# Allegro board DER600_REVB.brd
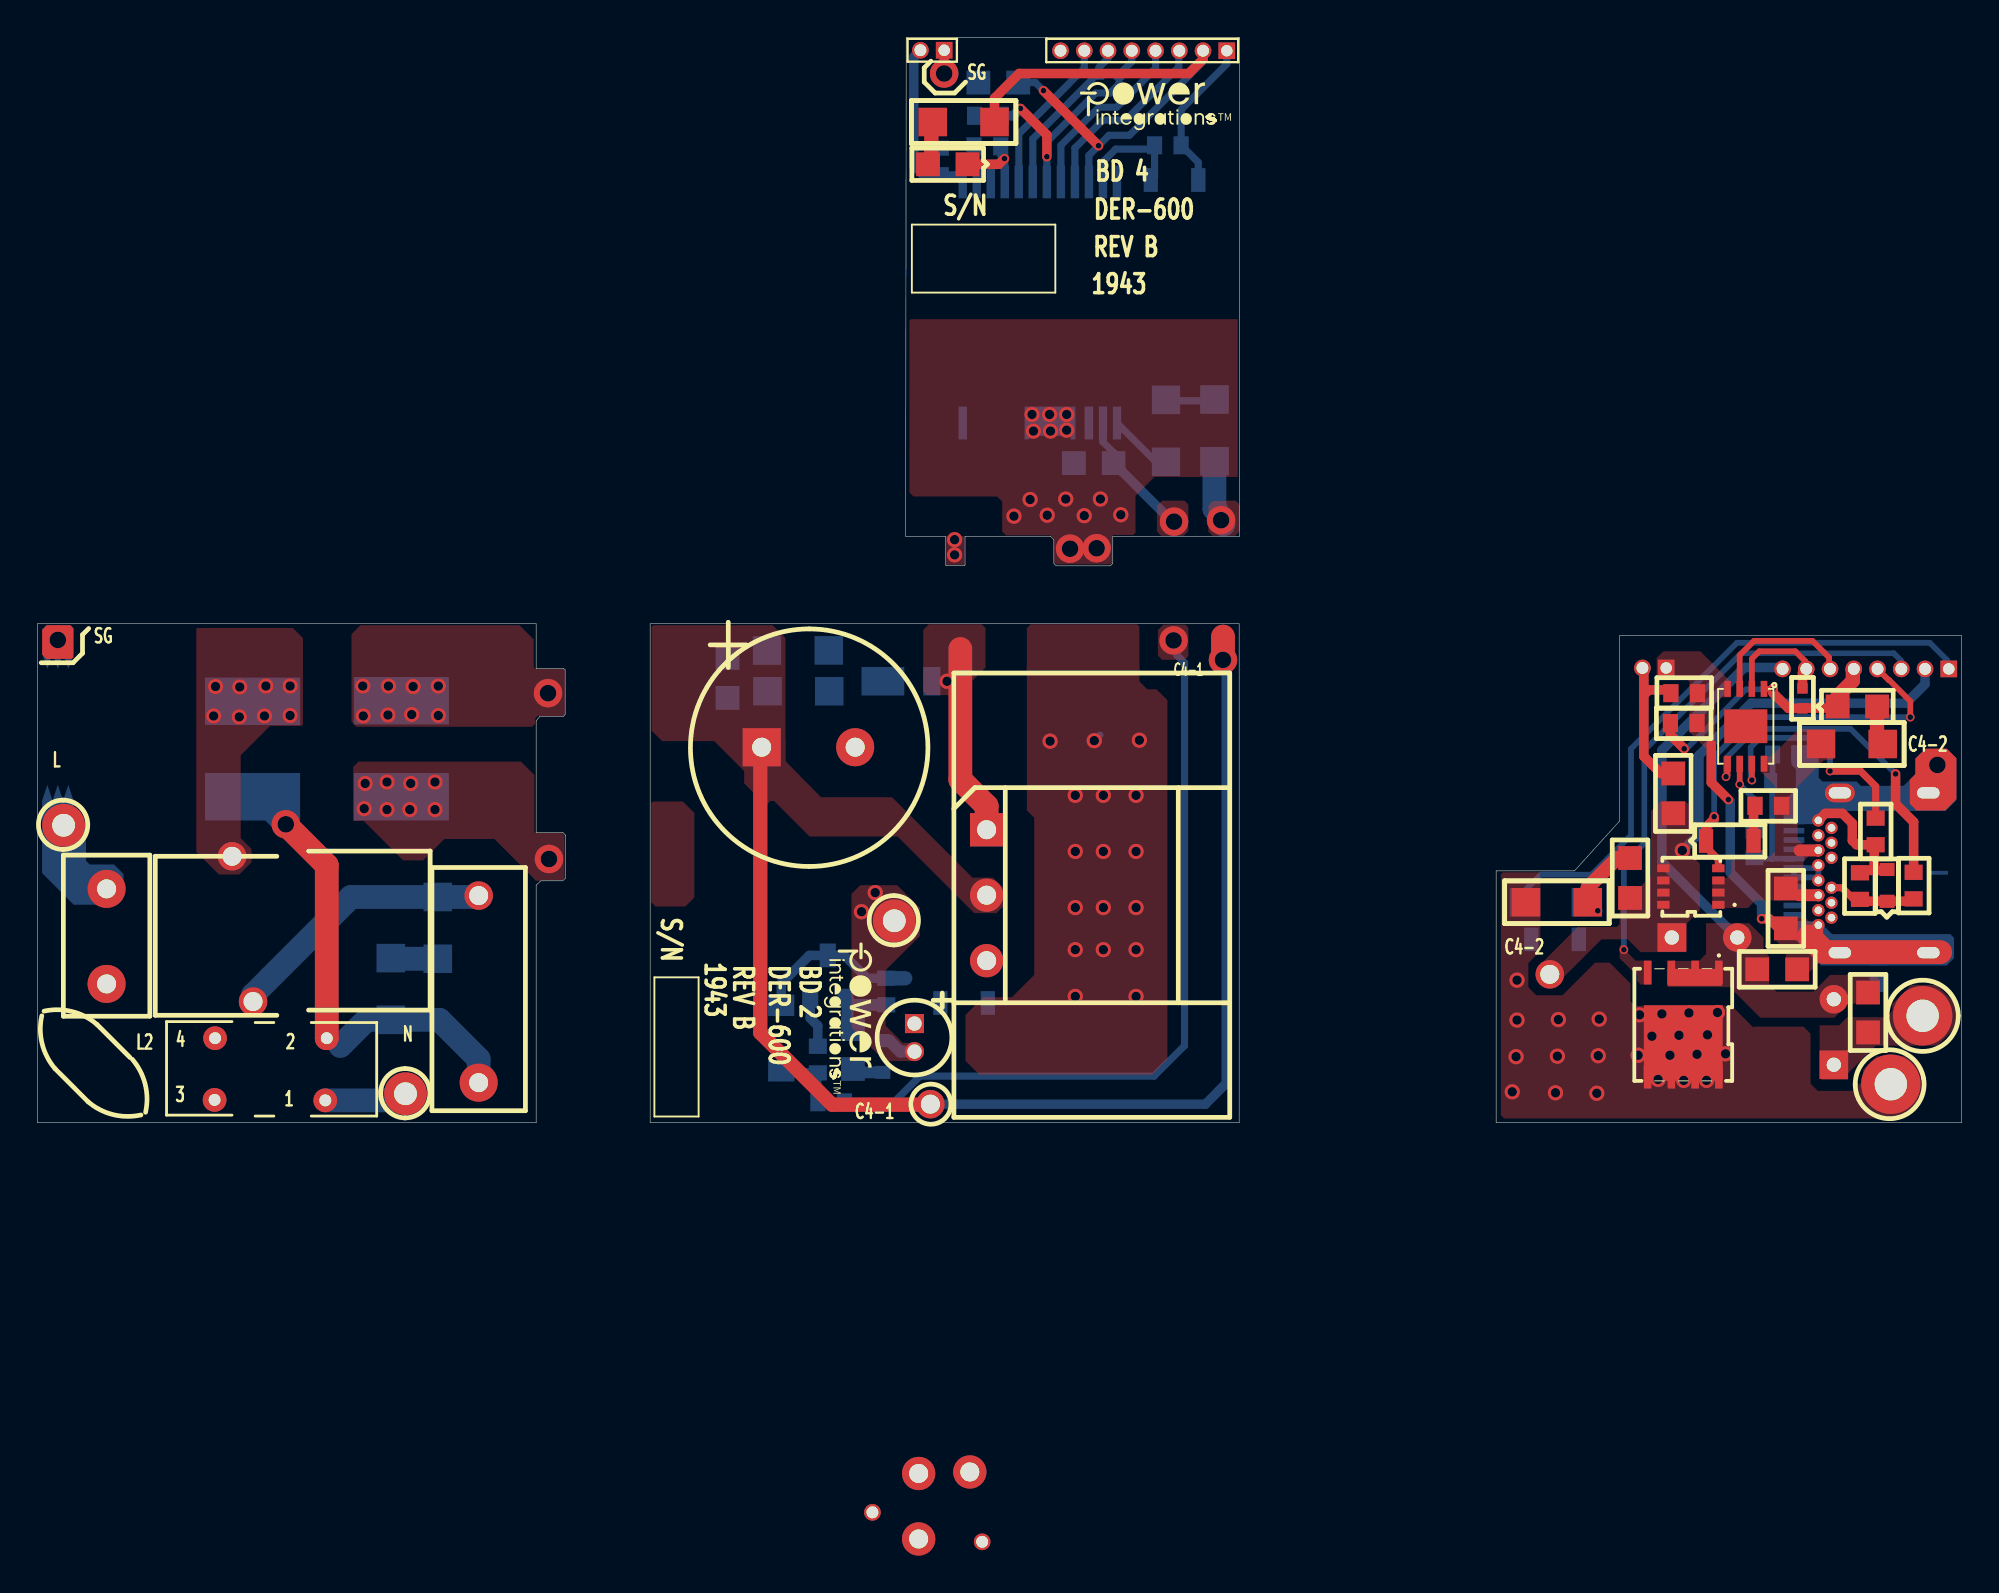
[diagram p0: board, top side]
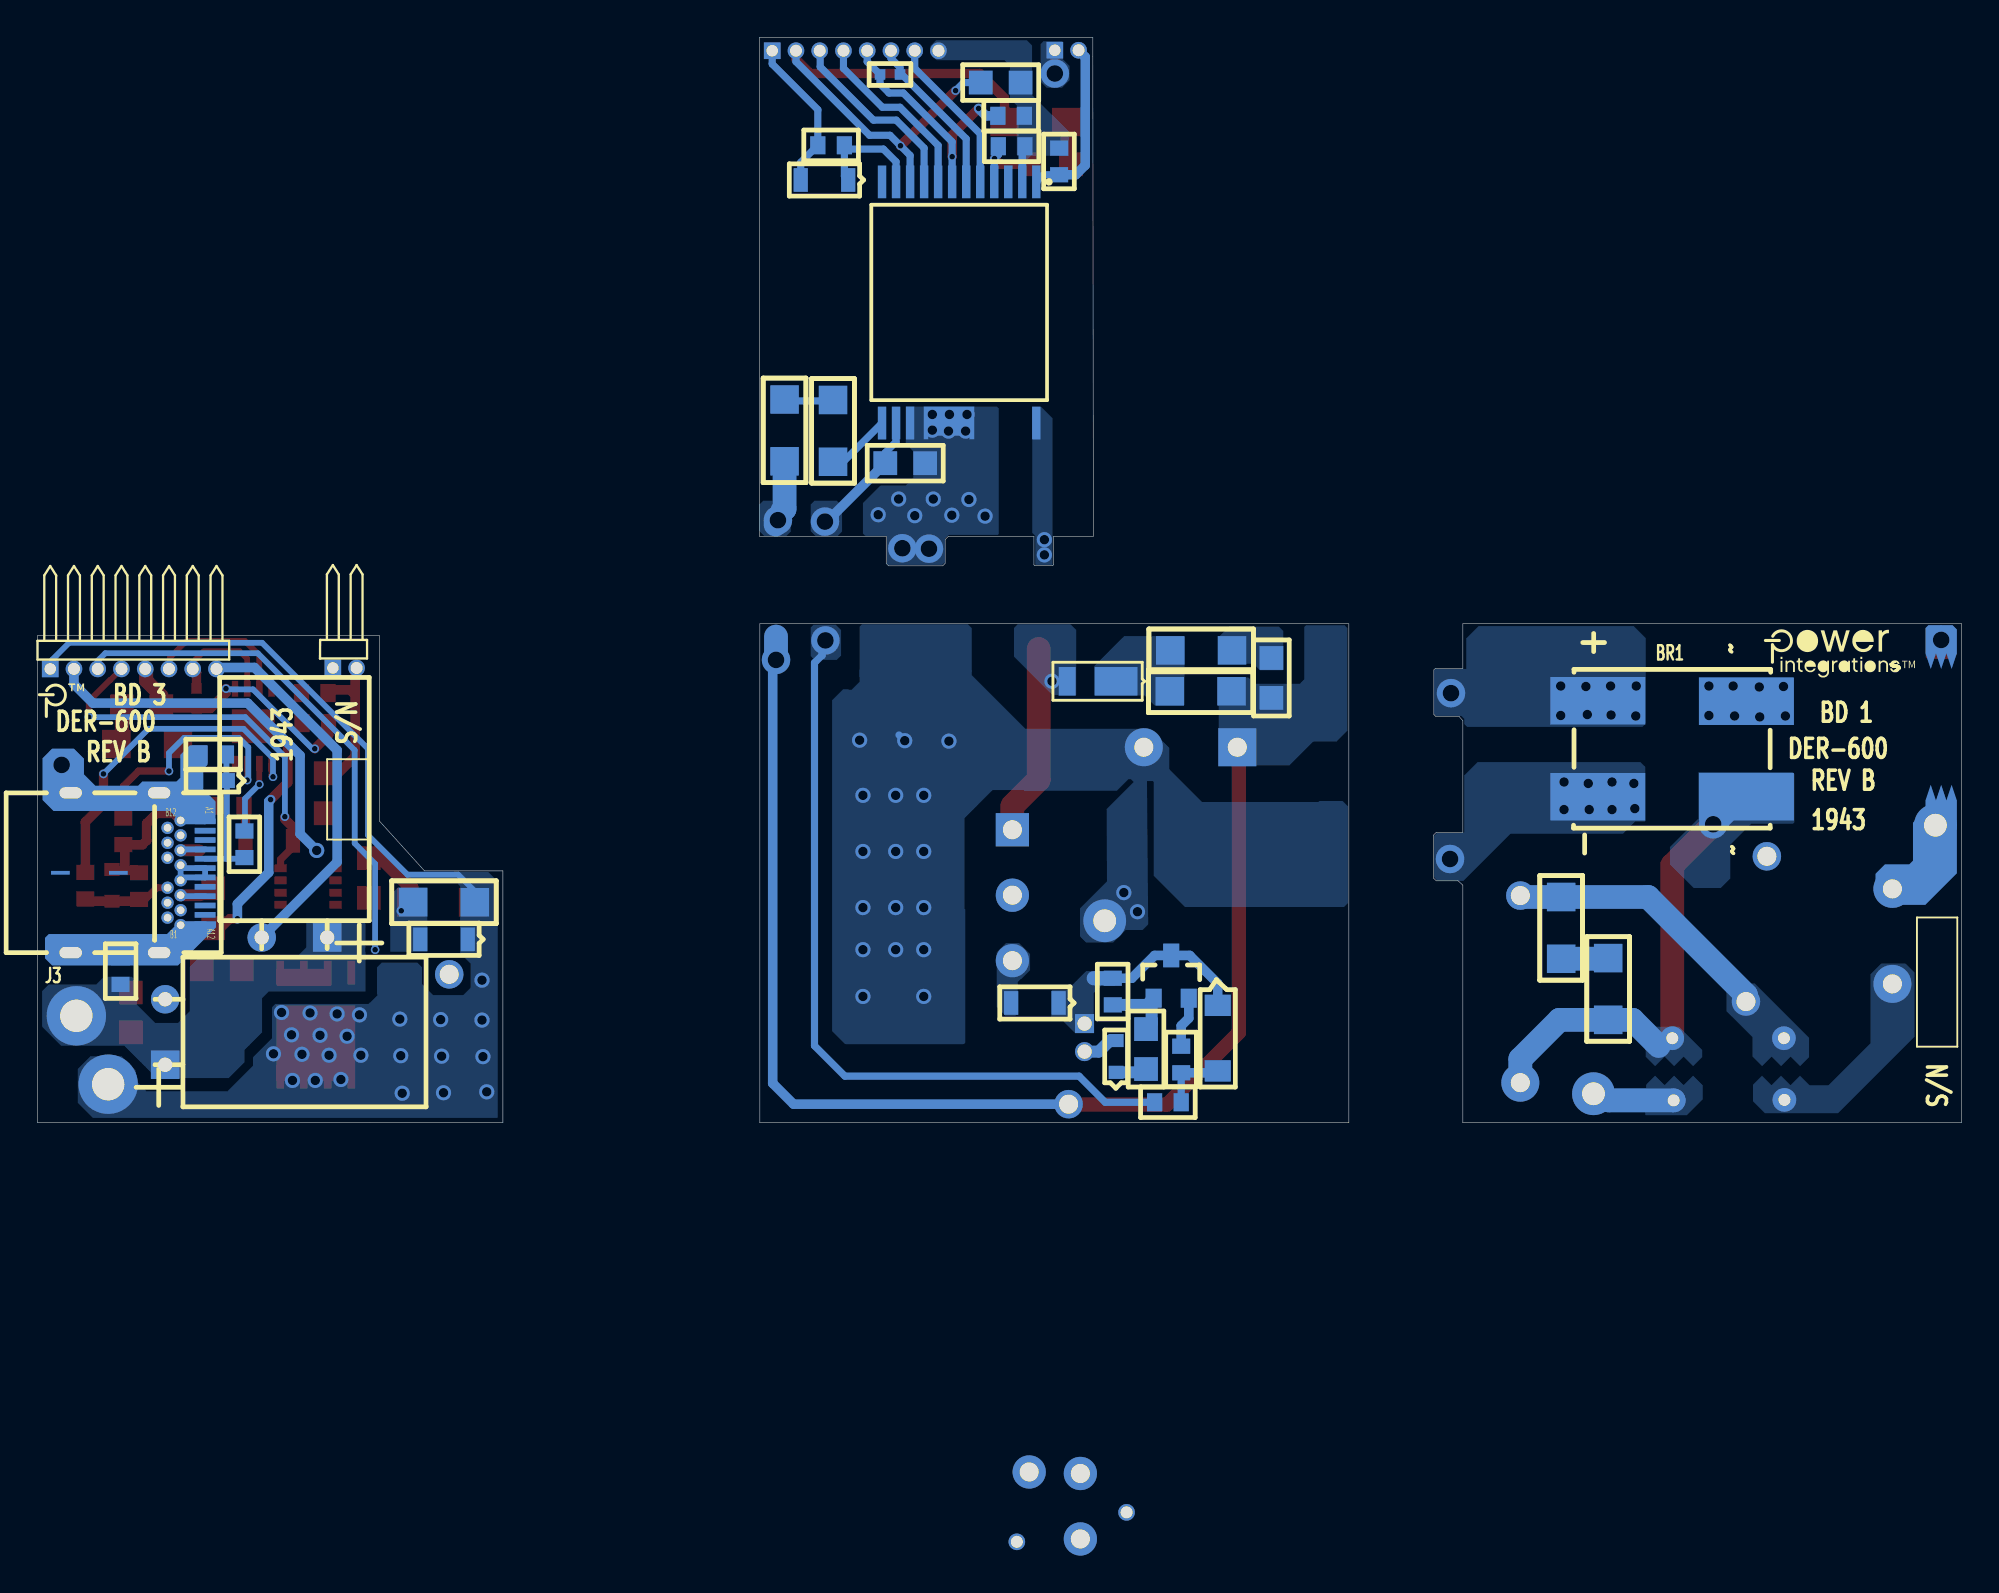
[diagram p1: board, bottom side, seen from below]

Outline 102.9 x 58.01 mm; copper layers: TOP, BOTTOM. Coordinates in mm from the lower left corner of the outline.
Outline path: 0,26.67 26.67,26.67 26.67,24.28 28.14,24.28 28.22,24.21 28.22,21.82 28.12,21.72 26.87,21.72 26.67,21.49 26.67,15.52 28.09,15.52 28.24,15.37 28.24,13.08 28.09,12.93 26.92,12.93 26.67,12.7 26.67,0 0,0 0,26.67 ; 32.77,26.67 64.26,26.67 64.26,0 32.77,0 32.77,26.67 ; 46.43,31.34 46.46,56.97 46.46,58.01 64.29,58.01 64.29,31.34 57.51,31.34 57.51,29.9 57.38,29.77 54.48,29.77 54.36,29.9 54.36,31.17 54.18,31.34 49.61,31.34 49.61,29.82 49.58,29.79 48.59,29.79 48.56,29.82 48.56,31.34 46.43,31.34 ; 78,13.46 82.19,13.46 84.61,16.13 84.61,26.04 102.9,26.04 102.9,0 78,0 78,13.46

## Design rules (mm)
constraint set DEFAULT: min track width 0.508

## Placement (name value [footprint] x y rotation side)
BR1  Z4DGP408L-HF  [PI_SM_D_Z4D]  19.51 22.53 90 bottom
C1  0.1 uF  [PINPXCAPRAD5X13X11P1MM040]  23.6 12.14 270 top
C2  56 uF  [PIPOLCAPCLYD500LS200040]  38.73 20.07 0 top
C3  2.2 nF  [PISMC0805]  36.91 22.71 90 bottom
C4  470 pF  [PINPCAPRAD7P5X11P5LS7P5MM030]  80.87 0.43 90 top
C5  6.8 uF  [PIPOLCAP4P0X11P0XLS1P5D030]  46.9 5.3 270 top
C6  4.7 uF  [PISMC0805]  57.56 35.26 180 bottom
C7  2.2 uF  [PISMC0603]  51.51 52.2 180 bottom
C8  4.7uF  [PISMC0603]  48.26 52.1 270 bottom
C9  3.3 uF-DNP  [PISMC0805]  50.32 55.6 0 bottom
C10  2.2 uF  [PISMC0603]  50.11 53.82 0 bottom
C11  1 nF  [PISMC0805]  85.17 14.15 270 top
C12  330 uF  [PIPOLCAPCYLD315LS138D030#2]  97.61 3.1 90 top
C14  2.2 uF  [PISMC0603]  87.33 21.36 0 top
C15  10 uF  [PISMC0805]  93.5 12.52 270 top
C16  560 pF  [PISMC0603]  94.21 19.68 180 bottom
C17  560 pF  [PISMC0603]  97.46 13.36 270 top
C19  2.2 uF  [PISMC0805]  97.89 6.96 270 top
C20  330 uF  [PIPOLCAPCYLD315LS138D030]  87.4 8.3 0 top
C21  1 uF  [PISMC0603]  98.45 7.39 90 bottom
D1  DFLF1800-7  [PISMDDFLR120012]  45.19 23.6 180 bottom
D2  BAV3004WS-7  [PISMSOD323]  48.29 6.4 0 bottom
D3  BAV19WS  [PISMSOD323]  79.88 9.8 0 bottom
D4  BAV21WS-7-F  [PISMSOD323]  89.23 15.06 0 top
D5  DZ2J240M0L  [PI_SM_D_SSMINI2P]  98.91 11.84 90 top
D6  DZ2J240M0L  [PI_SM_D_SSMINI2P]  92.68 18.29 0 bottom
D7  BAS416,115  [PISMDSOD323]  96.27 22.25 0 top
D8  BAS416,115-DNP  [PISMDSOD323]  49.73 51.23 180 top
D9  BAV19WS  [PISMSOD323]  59.54 50.39 0 bottom
F1  3.15 A  [PI_RST_MICROFUSE]  3.7 12.5 270 top
FL1  Hole_70mils  [PI_HOLE_70MIL]  100.84 5.71 90 top
FL2  Hole_70mils  [PI_HOLE_70MIL]  99.14 2.06 90 top
FL3  Hole_50mils  [PI_HOLE_50MIL]  45.82 10.79 0 top
J1  PCB Terminal 22 AWG  [PI_HOLE_22AWG]  1.4 15.9 0 top
J2  PCB Terminal 22 AWG  [PI_HOLE_22AWG]  19.68 1.55 0 top
J3  CON24_USB_C  [PI_CONN_USBC_WURTH]  95.94 13.36 270 bottom
J4  CON8  [PI_HDR_1P27MM_8RA]  63.6 57.3 180 top
J5  CON8  [PI_HDR_1P27MM_8RA]  102.21 24.26 180 bottom
J6  CON3  [PI_HDR_1P27MM_3RA]  48.49 57.33 180 top
J7  CON3  [PI_HDR_1P27MM_3RA#2]  87.1 24.31 180 bottom
L1  150 uH  [PI2P16P5X8P5X8P5LSD60]  12.75 6.02 90 top
L2  250 uH  [PI_TOROID_CMC4P_V_275UH]  13.64 0.36 180 top
NOREF  -  []  78 0 0 top
NOREF#2  -  []  64.29 31.34 90 top
NOREF#3  -  []  32.77 0 0 top
NOREF#4  -  []  102.9 0 90 top
NOREF#5  -  []  0 0 90 top
NOREF#6  -  []  -223.24 -184.18 0 top
NOREF#7  -  []  55.19 55.52 0 top
NOREF#8  -  []  44.53 10.19 270 top
NOREF#9  -  []  46.46 56.97 0 top
NOREF#10  -  []  0 26.67 0 top
NOREF#11  -  []  -154.42 52.58 0 top
NOREF#12  -  []  11.13 26.26 180 bottom
NOREF#13  -  []  102.77 23.7 180 bottom
Q1  MMBTA06LT1G  [PISMSOT23123_1]  41.33 6.65 180 bottom
Q2  AON6220  [PISMPQFN5X6B]  89.92 8.03 180 top
Q3  AON7520  [PISM8DFN_EP3P3X3P3A]  88.42 12.62 90 top
R1  1 M  [PISMR1206]  21.41 12.06 270 bottom
R2  1 M  [PISMR1206]  18.9 8.8 270 bottom
R4  2.00 M  [PISMR1206]  62.94 38.66 270 bottom
R5  1.80 M  [PISMR1206]  60.35 35.33 90 bottom
R6  20  [PISMR1206]  42.32 25.25 180 bottom
R7  680 k  [PISMR1206]  39.04 23.06 0 bottom
R8  100 k  [PISMR0603]  45.39 7.72 270 bottom
R9  5.1 k  [PISMR0805]  43.61 5 270 bottom
R10  3 k  [PISMR0603]  41.73 4.09 270 bottom
R11  47  [PISMR0603]  41.73 1.09 0 bottom
R12  20  [PISMR1206]  82.91 11.79 180 top
R13  20  [PISMR1206]  82.8 11.79 180 bottom
R14  47  [PISMR0603]  61.16 52.25 180 bottom
R15  0.009  [PISMR0805]  94.1 8.2 180 top
R16  324 k  [PISMR0805]  87.48 16.54 90 top
R17  10  [PISMR0603]  88.77 22.96 180 top
R18  4.70 k -DNP  [PISMR0402]  57.84 56.03 180 bottom
R19  4.70 k-DNP  [PISMR0402]  94.39 22.15 90 top
R20  1.5 k  [PISMR1206]  95.38 20.24 0 top
R21  1.5 k-DNP  [PISMR1206]  51.18 53.49 180 top
R22  100  [PISMR0603]  91.85 16.94 0 top
R23  22  [PISMR0603]  91.82 15.6 270 bottom
R24  22  [PISMR0603]  100.33 11.96 90 top
RT1  100 k  [PISMR0603]  98.3 14.86 90 top
T1  ATQ23.7/14  [PI_BOBBIN_ATQ23_7_H_6P]  56.38 12.16 0 top
U1  INN3368C-H301-TL  [PI_IC_INSOP_24D]  49.48 50.29 270 bottom
U2  VP302  [PI_SM_DFN-8]  92.33 23.19 180 top
VR1  MMSZ5261BT1G  [PI_SM_SOD-123_12]  39.78 6.27 270 bottom
VR2  DZ2S100M0L  [PI_SM_D_SSMINI2P]  45.21 2.69 90 bottom

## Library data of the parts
BR1 = DISCRETE BRIDGE_+~~-
C1 = CAP NP: alternate symbols: (pinpxcaprad5x13x11p1mm040h)
C2 = CAP POL: alternate symbols: (pipolcapclyd500ls2000401000lh)
C3 C4 C6 C8 C9 C19 = CAP NP
C5 = CAP POL: alternate symbols: (pipolcap4p0x11p0xls1p5d030h)
C7 C10 C14 C21 = CAP NP: alternate symbols: (pismc0603_1)
C11 = CAP NP: alternate symbols: (pismc0805_1)
C12 C20 = CAP POL: alternate symbols: (pipolcapcyld315ls138d030h)
C15 = CAP NP: alternate symbols: (pismc0805_1); room: 3
C16 C17 = CAP NP: room: 3
D1 = DIODE: alternate symbols: (pismddflr120012_1)
D2-D4 D7-D9 = DIODE
D5 D6 = DIODE_ZENER: room: 3
F1 = FUSE: alternate symbols: (pirstmicrofusehoz)
FL1-FL3 = FlyingLead
J1 J2 = TERM_1Pin
J3 = CON24_USB: room: 3
J4 J5 = CON8
J6 J7 = CON3
L1 = INDUCTOR
L2 = TORRID 4P_12_34: alternate symbols: (pi_toroid_CMC4p_V,pi_toroid_CMC4p_V_275uH)
Q1 = NPN_BEC
Q2 Q3 = FET_N_SGD_123_4_5678
R1 R2 R4-R22 = R
R23 R24 = R: room: 3
RT1 = THERMISTOR: room: 3
T1 = BATQ23_7_6P/GENERIC
U1 = InnoPro_p15
U2 = VP302: room: 3
VR1 VR2 = DIODE_ZENER

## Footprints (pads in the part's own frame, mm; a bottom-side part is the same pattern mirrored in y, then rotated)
PI2P16P5X8P5X8P5LSD60
  round 1.524 hole 1.016: 1(0.457,1.219) 2(8.221,2.337)
PI_BOBBIN_ATQ23_7_H_6P
  rect 1.778x1.778 hole 1.016: 1(-5.625,3.5)
  round 1.778 hole 1.016: 2(-5.625,0) 3(-5.625,-3.5) 4(-9.259,-34.412) 5(-9.259,-30.912) 6(-6.523,-30.831)
PI_CONN_USBC_WURTH
  oval 1.001x1.6 hole 0.599x1.199: (-4.27,-5.18) (-4.27,-0.45) (4.27,-5.18) (4.27,-0.45)
  round 0.66 hole 0.406: (-2,0.7) (2,0.7) B1(2.8,0.7) B2(2.4,0) B3(1.6,0) B4(1.2,0.7) B5(0.8,0) B6(0.4,0.7) B7(-0.4,0.7) B8(-0.8,0) B9(-1.2,0.7) B10(-1.6,0) B11(-2.4,0) B12(-2.8,0.7)
  rect 0.305x1.118 smd: A1(-2.75,2.01) A2(-2.25,2.01) A3(-1.75,2.01) A4(-1.25,2.01) A5(-0.75,2.01) A6(-0.25,2.01) A7(0.25,2.01) A8(0.75,2.01) A9(1.25,2.01) A10(1.75,2.01) A11(2.25,2.01) A12(2.75,2.01)
PI_HDR_1P27MM_3RA
  rect 0.889x0.889 hole 0.61: 1(0,0)
  round 0.889 hole 0.635: 2(1.27,0) 3(3.835,78.156)
PI_HDR_1P27MM_3RA#2
  rect 0.889x0.889 hole 0.61: 1(0,0)
  round 0.889 hole 0.635: 2(1.27,0) 3(36.576,-46.711)
PI_HDR_1P27MM_8RA
  rect 0.889x0.889 hole 0.61: 1(0,0)
  round 0.889 hole 0.635: 2(1.27,0) 3(2.54,0) 4(3.81,0) 5(5.08,0) 6(6.35,0) 7(7.62,0) 8(8.89,0)
PI_HOLE_22AWG
  round 2.286 hole 1.219: 1(0,0)
PI_HOLE_50MIL
  round 2.286 hole 1.219: 1(0,0)
PI_HOLE_70MIL
  round 3.175 hole 1.727: 1(0,0.025)
PI_IC_INSOP_24D
  rect 1.75x0.45 smd: 1(0,0) 2(0,-0.749) 3(0,-1.501) 4(0,-2.25) 5(0,-3) 6(0,-3.749) 7(0,-4.501) 8(0,-5.25) 9(0,-6) 10(0,-6.749) 11(0,-7.501) 12(0,-8.25) 13(12.89,-8.25) 14(12.89,-7.501) 15(12.89,-6.749) 24(12.89,0)
  custom 0.437x0.437 smd: 16(12.89,-4.671)
PI_RST_MICROFUSE
  round 2.032 hole 1.016: 1(0,0) 2(5.08,0)
PI_SM_D_SSMINI2P
  rect 0.699x0.8 smd: 1(0,0) 2(1.699,0)
PI_SM_D_Z4D
  rect 2.54x5.08 smd: 1(0.025,-0.051) 2(0,-8.001) 3(-5.105,-8.001) 4(-5.105,-0.051)
PI_SM_DFN-8
  rect 0.35x0.851 smd: 1(0,0) 2(0.65,0) 3(1.301,0) 4(1.951,0) 5(1.951,4) 6(1.301,4) 7(0.65,4) 8(0,4)
  rect 2.301x1.801 smd: 9(0.975,1.999)
PI_SM_SOD-123_12
  rect 1.143x1.397 smd: 1(0,0) 2(3.505,0)
PI_TOROID_CMC4P_V_275UH
  round 1.27 hole 0.635: 1(-1.753,-0.838) 2(-1.829,-4.162) 3(4.168,-0.864) 4(4.143,-4.162)
PINPCAPRAD7P5X11P5LS7P5MM030
  round 1.524 hole 1.016: 1(0.559,33.122) 2(7.5,0)
PINPXCAPRAD5X13X11P1MM040
  round 1.524 hole 1.016: 1(0,0)
  round 2.032 hole 1.016: 2(10,0)
PIPOLCAP4P0X11P0XLS1P5D030
  rect 1.016x1.016 hole 0.762: 1(0,0)
  round 1.016 hole 0.762: 2(1.5,0)
PIPOLCAPCLYD500LS200040
  rect 2.032x2.032 hole 1.016: 1(0,0)
  round 2.032 hole 1.016: 2(5,0)
PIPOLCAPCYLD315LS138D030
  rect 1.524x1.524 hole 0.762: 1(0,1.6)
  round 1.524 hole 0.762: 2(3.5,1.6)
PIPOLCAPCYLD315LS138D030#2
  rect 1.524x1.524 hole 0.762: 1(0,1.549)
  round 1.524 hole 0.762: 2(3.5,1.549)
PISM8DFN_EP3P3X3P3A
  rect 0.419x0.66 smd: 1(-0.975,-1.471) 2(-0.325,-1.471) 3(0.325,-1.471) 4(0.975,-1.471) 5(0.975,1.471) 6(0.325,1.471) 7(-0.325,1.471) 8(-0.975,1.471)
PISMC0603
  rect 0.813x0.965 smd: 1(0,0) 2(1.422,0)
PISMC0805
  rect 1.27x1.27 smd: 1(0,0) 2(2.134,0)
PISMDDFLR120012
  rect 2.286x1.524 smd: 1(-0.025,0)
  rect 0.914x1.524 smd: 2(-2.642,0)
PISMDSOD323
  rect 1.27x1.27 smd: 1(0,0) 2(2.108,0)
PISMPQFN5X6B
  rect 0.406x1.27 smd: 1(0,0) 2(1.27,0) 3(2.54,0) 4(3.81,0)
  rect 0.406x1.219 smd: 5(3.81,5.588) 6(2.54,5.588) 7(1.27,5.588) 8(0,5.588)
PISMR0402
  rect 0.559x0.559 smd: 1(0,0) 2(1.067,0)
PISMR0603
  rect 0.813x0.965 smd: 1(0,0) 2(1.422,0)
PISMR0805
  rect 1.27x1.27 smd: 1(0,0) 2(2.134,0)
PISMR1206
  rect 1.524x1.524 smd: 1(0,0) 2(3.302,0)
PISMSOD323
  rect 0.762x1.27 smd: 1(0,0) 2(2.54,0)
PISMSOT23123_1
  rect 0.864x1.016 smd: 1(-1.88,0) 2(0,0)
  rect 0.864x1.27 smd: 3(-0.94,2.286)

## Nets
GND: C14.2 C15.2 C16.1 C17.1 C21.2 D5.2 D6.2 J3.A1 J3.A12 J3.B1 J3.B12 J6.1 J7.1 R15.1 R17.1 RT1.1 U2.4
GND_SIGNAL: C7.2 C8.1 C9.1 C10.1 C12.2 C19.1 C20.2 J4.8 J5.8 Q2.1 Q2.2 Q2.3(S3) R15.2 U1.2
VBUS_IN: C4.2 C9.2 C11.2 C12.1 C19.2 C20.1 C21.1 FL1.1 J4.2 J5.2 Q3.5 Q3.6 Q3.7 Q3.8 R16.1 R21.1 U1.10(VOUT)
VBUS_OUT: C15.1 J3.A4 J3.A9 J3.B4 J3.B9(VBUS4) Q3.1 Q3.2 Q3.3(S3) R20.1 R22.2 U2.8
BPS: C7.1 D8.1 U1.4
CC1: C16.2 D6.1 J3.A5 R23.2
CC2: C17.2 D5.1 J3.B5 R24.1
D: D3.1 D9.2 FL2.1 J4.1 J5.1 Q2.5 Q2.6 Q2.7 Q2.8 R12.2 R13.2 R14.1
IS: C8.2 J6.2 J7.2 R16.2 R17.2 U1.1
NC3: U1.3
NTC: RT1.2 U2.7
SCL: J4.7 J5.7 R19.2 U1.5 U2.2
SDA: J4.6 J5.6 R18.2 U1.6 U2.3
SR: J4.3 J5.3 Q2.4 U1.9
UVCC: C10.2 C14.1 D7.1 J4.5 J5.5 R18.1 R19.1 U1.7 U2.1(VCC)
V-PIN: R5.1 U1.13
VB/D: D4.1 J4.4 J5.4 Q3.4 U1.8
N10479111: F1.1 J1.1
N10805923: BR1.4 C2.2 C5.2 C6.2 FL3.1 U1.15 U1.16 VR2.2
N10806149: C6.1 R11.2 U1.14
N10813018: R4.1 R5.2
N10873526: D9.1 R14.2 U1.11
N10950085: R10.2 R11.1 VR1.2
N10950141: Q1.2(EMITTER) R10.1
N10950189: Q1.1 R8.2 R9.1
N10961861: BR1.1 C2.1 C3.1 C4.1 R4.2 R7.1 T1.2
N10966650: D1.2 T1.1 U1.24
N11036082: D1.1 R6.1 R7.2
N11077448: C5.1 D2.1 Q1.3 R8.1 VR1.1
N11099981: BR1.2 L1.2
N11100009: C1.1 L1.1 L2.4 R1.1
N11100013: BR1.3(AC2) C1.2 L2.2 R2.2
N11100133: J2.1 L2.1
N11120095: D2.2 T1.3
N11139619: C3.2 R6.2
N11156493: C11.1 D3.2 R12.1 R13.1
N11381159: R1.2 R2.1
N12152275: D4.2 R22.1
N12168266: R9.2 VR2.1
N12183858: R23.1 U2.6
N12183920: R24.2 U2.5
N12183972: J3.A6 J3.A7 J3.B6 J3.B7
N12291187: D7.2 R20.2
N12330267: F1.2 L2.3
N12333123: D8.2 R21.2

Pads without a net: J3 A2 A3 A8 A10 A11 B2 B3 B8 B10 B11; J6 3; J7 3; T1 4 5 6; U1 12; U2 9

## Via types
v1: diameter 0.457, hole 0.305, TOP to BOTTOM, 18 vias
v2: diameter 0.813, hole 0.508, TOP to BOTTOM, 84 vias
v3: diameter 1.524, hole 0.889, TOP to BOTTOM, 12 vias

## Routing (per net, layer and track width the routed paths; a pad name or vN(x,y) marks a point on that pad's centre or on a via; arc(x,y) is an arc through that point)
GND: length 36.1
  TOP w0.508: C15.2 93.12,10.39 92.6,10.9 v1(92.2,10.9) ; J6.1 v3(48.49,56.08) ; J3.B1 95.24,9.59 95.71,9.12 ; 98.22,13.49 98.22,14.78 RT1.1 97.28,14.86 97.05,15.09 97.05,16 96.52,16.54 95.61,16.54 J3.B12 ; 98.22,13.49 97.59,13.49 C17.1 ; 98.22,13.49 98.86,13.49 D5.2 ; 89.51,20.24 89.51,18.19 v1(90.42,17.27)
  TOP w0.762: 87.06,24.27 J7.1
  TOP w1.27: 101.75,9.12 95.58,9.12 94.74,9.96
  BOTTOM w0.305: J3.B12 95.19,16.11 J3.A1 93.93,16.81 94.26,17.14 94.26,18.16 D6.2 94.21,18.46 C16.1 ; J3.B1 95.19,10.61 J3.A12
  BOTTOM w0.508: v1(90.42,17.27) 90.53,17.17 90.53,13.37 92.2,11.7 v1(92.2,10.9)
  vias: v3(1.09,25.81)
GND_SIGNAL: length 23
  TOP w0.305: J5.8 93.32,24.28 93.22,24.38
  BOTTOM w0.381: U1.2 50.23,52.06 50.22,52.07 ; 50.22,52.07 50.22,51.18 ; 50.22,52.07 C7.2
  BOTTOM w0.508: C20.2 86.87,13.93 86.87,19.91 91.29,24.33 93.24,24.33 J5.8
VBUS_IN: length 49.8
  TOP w0.508: R21.1 51.18,54.76 52.5,56.08 61.57,56.08 62.33,56.85 J4.2 ; 80.87,8.17 C4.2 ; v1(53.8,55.17) v1(56.74,52.22)
  BOTTOM w0.381: v1(53.8,55.17) 53.37,55.6 C9.2 ; J4.2 62.33,56.72 58.39,52.78 57.3,52.78 v1(56.74,52.22) 56.23,51.71 U1.10
  BOTTOM w0.508: J5.2 100.94,23.44 99.92,22.43 91.64,22.43 88.85,19.63 88.85,15.44 v2(87.96,14.55)
VBUS_OUT: length 4.7
  TOP w0.635: 94.23,14.55 95.23,14.55 J3.B9 ; 94.2,12.16 J3.B4
  BOTTOM w0.305: J3.B9 95.19,14.61 J3.A4 ; J3.B4 95.19,12.11 J3.A9
  vias: v3(101.6,19.13)
BPS: length 4.4
  TOP w0.508: v1(51.71,51.54) 51.41,51.23 D8.1
  BOTTOM w0.381: C7.1 51.51,51.77 ; 51.51,51.77 51.73,51.54 51.73,50.29 U1.4 ; 51.51,51.77 51.51,51.74 v1(51.71,51.54)
CC1: length 7.8
  BOTTOM w0.305: R23.2 91.88,14.11 92.76,14.11 ; 92.76,14.11 92.76,18.21 D6.1 92.79,18.39 C16.2 ; 92.76,14.11 J3.A5
CC2: length 4.7
  TOP w0.381: C17.2 97.13,11.94 96.51,12.56 J3.B5
  TOP w0.508: C17.2 97.56,11.84 D5.1 100.2,11.84 R24.1
D: length 40.7
  BOTTOM w0.305: 102.16,24.33 102.16,24.31 J5.1 102.11,24.74 101.19,25.65 90.88,25.65 85.22,19.99 85.22,15.37 83.11,13.26 80.39,13.26 79.5,12.37 R13.2
  BOTTOM w0.381: J4.1 63.6,56.59 61.16,54.15 R14.1 62.08,51.33 D9.2
  vias: v2(78.87,1.65) v2(79.12,7.62) v2(79.12,5.49) v2(79.07,3.53) v2(81.18,1.6) v2(81.33,5.51) v2(81.28,3.56) v2(83.39,1.57) v2(83.52,5.54) v2(83.46,3.58) v2(85.6,3.61) v2(85.67,5.77) v2(86.33,4.62) v2(86.66,2.31) v2(86.87,5.82) v2(87.3,3.61) v2(87.78,4.67) v2(88.04,2.26) v2(88.32,5.87) v2(88.75,3.66) v2(89.31,4.7) v2(89.26,2.26) v2(89.84,5.89) v2(90.27,3.68)
IS: length 17.6
  TOP w0.508: 85.87,24.27 85.9,24.23 85.9,22.86 ; R16.2 86.82,18.67 85.9,19.58 85.9,22.86 ; R17.2 87.17,23.14 86.18,23.14 85.9,22.86
  TOP w0.762: J7.2 85.87,24.27
  BOTTOM w0.381: U1.1 49.1,50.67 C8.2
  BOTTOM w0.508: J6.2 46.86,56.97 46.86,51.18 47.37,50.67 C8.2
NTC: length 12.9
  TOP w0.305: U2.7 v1(91.68,18.31)
  TOP w0.381: RT1.2 98.3,17.98 97.49,18.8 v1(95.86,18.8)
  BOTTOM w0.305: v1(95.86,18.8) 95.86,19.76 95.05,20.57 92.13,20.57 91.62,20.07 91.62,18.37 v1(91.68,18.31)
SCL: length 14.9
  TOP w0.305: J5.7 94.54,24.31 94.54,24.66 94.01,25.2 92.08,25.2 91.68,24.8 U2.2
  TOP w0.508: R19.2 94.39,24.05 J5.7
  BOTTOM w0.381: J4.7 55.98,56.36 52.48,52.86 U1.5
SDA: length 16.7
  TOP w0.305: U2.3 91.03,24.99 91.8,25.76 94.92,25.76 95.81,24.87 95.81,24.31 J5.6
  BOTTOM w0.381: J4.6 57.25,56.9 56.77,56.41 R18.2 56.74,56.06 56.69,56.06 53.23,52.59 U1.6
SR: length 37.6
  BOTTOM w0.305: v1(84.84,9.25) 84.84,13.84 85.93,14.94 85.93,19.91 91.11,25.1 99.26,25.1 99.67,24.69 J5.3
  BOTTOM w0.381: U1.9 55.48,52.1 56.97,53.59 58.19,53.59 61.04,56.44 61.04,57.28 J4.3
UVCC: length 28.4
  TOP w0.305: U2.1 92.8,23.19
  TOP w0.508: 92.8,23.19 v1(92.81,23.2) 92.81,22.97 93.64,22.15 R19.1 94.4,22.17 96.22,22.17 D7.1 ; C14.1 87.33,20.73 v1(88.06,19.99) ; v1(52.57,54.22) 53.98,52.8 v1(53.98,51.64)
  TOP w0.762: J5.5 97.08,24.21 97.08,23.62 96.27,22.81 D7.1
  BOTTOM w0.305: v1(88.06,19.99) 88.19,19.99 91.36,23.16 92.77,23.16 v1(92.81,23.2)
  BOTTOM w0.381: U1.7 v1(53.98,51.64) 53.98,52.43 56.59,55.04 57.35,55.04 57.84,55.52 R18.1 58.52,56.72 J4.5
  BOTTOM w0.508: v1(52.57,54.22) 52.17,53.82 C10.2
V-PIN: length 3.5
  BOTTOM w0.381: R5.1 59.8,35.33 U1.13
VB/D: length 30.8
  TOP w0.305: J5.4 99,23.66 99.03,23.66 100.15,22.53 v1(100.15,21.68)
  TOP w0.381: D4.1 89.23,14.73 89.89,14.07 Q3.4
  TOP w0.508: v1(89.66,16.36) 89.66,16.23 89.23,15.8 D4.1
  BOTTOM w0.305: v1(89.66,16.36) 89.66,19.56 91.78,21.68 v1(100.15,21.68)
  BOTTOM w0.381: J4.4 59.79,56.36 57.71,54.28 56.77,54.28 54.73,52.24 U1.8
N10805923: length 2.9
  BOTTOM w0.381: 56.82,20.73 v2(56.52,20.42)
  BOTTOM w0.508: 55.65,30.61 55.27,30.61 55.22,30.66 v3(55.22,30.68) ; C2.2 43.73,20
  BOTTOM w0.635: C5.2 46.14,3.8 45.54,4.39 VR2.2
  vias: v2(17.53,18.14) v2(17.48,16.79) v2(18.69,18.21) v2(18.69,16.74) v2(19.91,16.74) v2(19.96,18.14) v2(21.26,18.21) v2(21.26,16.74) v2(44.07,11.28) v2(44.8,12.3) v2(52.22,32.42) v2(53.08,33.31) v2(53.19,37.86) v2(53.26,36.97) v2(54,32.47) v2(54.12,37.86) v2(54.18,36.97) v2(54.15,20.4) v2(55.04,37.86) v2(55.04,37.02) v2(54.99,33.34) v2(55.5,17.5) v2(55.5,14.5) v2(55.5,11.5) v2(55.5,9.25) v2(55.5,6.75) v2(55.98,32.45) v2(56.84,33.34) v2(57,17.5) v2(57,14.5) v2(57,11.5) v2(57,9.25) v2(57.93,32.5) v2(58.75,17.5) v2(58.75,14.5) v2(58.75,11.5) v2(58.75,9.25) v2(58.75,6.75) v2(58.93,20.45) v3(27.36,14.1) v3(56.64,30.71)
N10806149: length 48.4
  BOTTOM w0.381: C6.1 57.56,35.81 56.98,36.39 U1.14 ; R11.2 45.8,1.09 47.19,2.49 59.72,2.49 61.34,4.11 61.34,24.58 60.96,24.97 60.93,24.97 60.93,25.6 v3(60.76,25.78)
  BOTTOM w0.508: v3(60.78,32.13) 60.78,32.31 60.71,32.38 60.3,32.38 60.3,32.51 C6.1
N10813018: length 2.6
  BOTTOM w0.381: R4.1 62.87,38.58 60.4,38.58 R5.2
N10873526: length 6.1
  BOTTOM w0.381: D9.1 59.74,50.6 R14.2 59.54,52.04 57.66,52.04 56.98,51.37 U1.11
N10950085: length 3.6
  BOTTOM w0.381: R11.1 R10.2
  BOTTOM w0.508: VR1.2 39.88,2.67 R10.2
N10950141: length 2.7
  BOTTOM w0.508: R10.1 41.73,5.18 41.33,5.59 Q1.2
N10950189: length 4
  BOTTOM w0.508: 43.31,6.55 Q1.1
  BOTTOM w0.635: R9.1 43.31,5.3 43.31,6.55 43.56,6.3 R8.2
N10961861: length 71.2
  TOP w0.508: 63.3,32.03 v3(63.3,32.21)
  TOP w0.762: C4.1 47.73,0.97 42.49,0.97 38.65,4.8 38.65,19.59 38.73,19.66
  TOP w1.27: C2.1 38.73,19.66 ; v3(63.4,24.74) 63.4,25.98
  BOTTOM w0.305: 38.91,20.25 38.99,20.33
  BOTTOM w0.508: C4.1 62.46,0.99 63.58,2.11 63.58,24.56 v3(63.4,24.74) ; 63.47,32.03 63.4,32.11
  BOTTOM w0.635: 47.6,0.84 C4.1
  BOTTOM w1.27: 63.4,32.11 v3(63.3,32.21) 63.3,32.11 63.42,31.98 ; 63.07,32.69 62.94,32.82 R4.2 ; v3(63.4,24.74) 63.4,25.98
  vias: v2(17.4,23.34) v2(17.42,21.74) v2(18.75,21.79) v2(18.77,23.34) v2(20.02,21.82) v2(20.09,23.32) v2(21.44,23.34) v2(21.44,21.77) v3(27.3,22.96)
N10966650: length 10.2
  TOP w1.27: T1.1 50.76,16.93 49.35,18.34 49.35,25.32
  vias: v2(48.64,23.6) v2(49.05,31.17) v2(49.05,30.35)
N11077448: length 8.9
  BOTTOM w0.508: VR1.1 39.78,7.44 41.27,8.94 Q1.3 43.15,8.94 44.37,7.72 R8.1
  BOTTOM w0.762: R8.1 46.41,7.72
N11099981:
  vias: v2(9.42,21.74) v2(9.53,23.32) v2(10.82,23.29) v2(10.79,21.69) v2(12.14,21.74) v2(12.22,23.34) v2(13.51,23.34) v2(13.51,21.77)
N11100009: length 14.6
  BOTTOM w1.27: L1.1 11.53,6.83 16.76,12.06 R1.1 23.52,12.06 C1.1
N11100013: length 25.3
  TOP w1.27: v3(13.28,15.95) 15.47,13.76 L2.2
  BOTTOM w0.305: 23.26,1.8 C1.2
  BOTTOM w1.27: BR1.3 11.81,17.42 v3(13.28,15.95) ; C1.2 23.6,3.4 21.5,5.5 R2.2 17.6,5.5 16.2,4.1
N11100133: length 4.4
  BOTTOM w1.27: J2.1 19.23,1.55 18.87,1.19 L2.1
N11156493: length 4.5
  TOP w0.762: C11.1 84.48,14.15 82.91,12.57 R12.1
  BOTTOM w0.508: v1(83.44,11.33) 83.26,11.33 R13.1
N11381159: length 2.5
  BOTTOM w1.27: R1.2 18.94,8.76 R2.1
N12152275: length 1.9
  TOP w0.508: R22.1 91.77,16.87 D4.2
N12168266: length 1.7
  BOTTOM w0.635: R9.2 43.79,2.69 VR2.1
N12183858: length 3.9
  TOP w0.305: v1(91.03,18.08) U2.6
  BOTTOM w0.305: R23.1 91.8,15.62 91.8,17.32 v1(91.03,18.08)
N12183920: length 18.1
  TOP w0.305: U2.5 90.38,18.57 v1(90.3,18.49)
  TOP w0.508: v1(99.36,18.64) 99.36,17.04 100.33,16.08 R24.2
  BOTTOM w0.305: v1(90.3,18.49) 90.3,19.48 91.87,21.06 96.95,21.06 v1(99.36,18.64)
N12183972: length 4
  BOTTOM w0.305: 95.09,13.11 J3.B6 J3.B7 95.09,13.61 J3.A6 J3.A7 95.09,13.11
N12291187: length 2.1
  TOP w0.762: R20.2 98.37,20.55 D7.2
N12333123: length 2.4
  TOP w0.762: R21.2 47.8,53.42 47.8,51.41 D8.2

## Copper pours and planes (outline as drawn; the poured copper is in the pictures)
GND on TOP (solid shape): 1.92,26.42 1.92,24.88 1.83,24.79 0.48,24.79 0.25,25.02 0.25,26.34 0.51,26.59 1.75,26.59
GND on BOTTOM (solid shape): 1.93,26.44 1.93,25.1 1.65,24.26 1.37,25.1 1.09,24.26 0.81,25.1 0.53,24.26 0.25,25.1 0.25,26.37 0.48,26.59 1.78,26.59
GND on BOTTOM (solid shape): 95.53,10.64 95.53,10.52 95.96,10.08 102.29,10.08 102.49,9.88 102.49,8.79 102.11,8.41 95.38,8.41 93.34,10.44 93.34,10.77 93.37,10.74 95,10.74 95.07,10.82 95.35,10.82
GND on TOP: 94.7,7.6 94.7,8 95.2,8.5 95.5,8.5 95.5,9.4 95,9.9 93.5,9.9 93.5,7.6
GND on TOP: 95.35,10.74 95.48,10.62 95.48,10.21 94.28,9.02 93.68,9.02 92.9,9.8 92.9,10.97 94.51,10.97 94.74,10.74
GND on TOP: 88.34,23.57 88.34,20.88 89.43,19.79 89.61,19.79 89.74,19.91 89.74,22.43 90.04,22.73 90.55,22.73 90.55,23.57 88.93,25.2 86.94,25.2 86.59,24.84 86.59,23.95 86.66,23.88 88.04,23.88
GND on BOTTOM: 48.08,57.81 49.1,57.81 49.25,57.66 49.25,55.65 48.92,55.32 48.11,55.32 47.7,55.73 47.7,56.49 48.08,56.87
GND_SIGNAL on TOP (solid shape): 90.09,7.32 87.17,7.32 87.17,8.23 90.09,8.23
GND_SIGNAL on TOP: 92.6,8.89 92.6,7.4 93,7 94.96,7 95.86,7.9 98.27,7.9 98.5,7.67 98.5,6.5 98.37,6.38 96.85,6.38 96.09,5.61 92.13,5.61 90.49,7.25 87.21,7.25 87.17,7.29 87.17,8.64 87.43,8.64 87.45,8.65 88.85,8.65 89.23,9.03 89.23,10.67 91.53,10.67 92.3,9.9 92.3,9.19
GND_SIGNAL on BOTTOM: 49.71,54.94 47.75,52.98 47.75,51.69 49.76,51.69 50.01,51.44 50.01,50.85 50.42,50.85 50.46,50.89 50.46,51.68 50.52,51.74 50.52,54.37 50.89,54.74 50.89,56.5 51.18,56.79 54.81,56.79 55.14,57.12 55.14,57.56 54.84,57.86 49.99,57.86 49.71,57.58
VBUS_IN on TOP: 88.39,14.35 88.9,13.84 88.9,11.35 88.21,10.67 88.21,9.14 88.19,9.12 85.72,9.12 85.04,9.8 83.64,9.8 81.13,7.29 80.62,7.29 80.24,7.67 80.24,8.33 82.37,10.46 84.45,10.46 84.61,10.62 84.61,12.62 85.72,12.62 86.28,13.18 86.28,16.66 86.82,17.2 88.11,17.2 88.39,16.92
VBUS_IN on TOP: 96.34,5.21 96.77,5.64 98.86,5.64 99.19,5.97 99.19,6.35 100.2,7.37 101.57,7.37 102.72,6.22 102.72,5.23 101.6,4.11 98.3,4.11 96.82,2.64 96.82,2.29 95.43,2.29 95.3,2.41 95.3,5.21
VBUS_IN on BOTTOM: 85.34,10.62 85.34,7.01 90.53,7.01 90.88,6.65 90.88,4.83 91.82,3.89 91.82,3.23 92.66,2.39 96.82,2.39 96.82,2.69 98.25,4.11 101.63,4.11 102.64,5.13 102.64,7.04 102.29,7.39 99.75,7.39 99.34,7.8 97.84,7.8 97.59,7.54 97.59,6.32 96.6,5.33 95.38,5.33 94.74,5.97 94.74,8.33 94.25,8.83 89.07,8.83 88.52,9.37 88.52,10.69 88.44,10.77 85.5,10.77
VBUS_OUT on BOTTOM (solid shape): 95.25,19.66 95.25,18.44 95.45,18.24 97.28,18.24 97.51,18.01 99.8,18.01 100.39,18.61 100.41,18.61 100.41,19.46 100.94,19.99 102.11,19.99 102.62,19.48 102.62,17.25 102.03,16.66 95.81,16.66 95.49,16.34 95.49,16.01 95.35,15.88 95.12,15.88 95.02,15.98 93.4,15.98 93.37,16 93.37,17.17 94.03,17.83 94.03,18.9 93.8,19.13 93.8,20.17 94.74,20.17
VBUS_OUT on TOP: 89.56,13.16 90.4,13.16 90.58,13.34 90.58,13.94 90.68,14.05 92.46,14.05 92.91,14.5 92.91,18.01 92.15,18.77 92.15,19.53 92.2,19.58 92.71,19.58 94.13,21.01 94.13,21.06 96.11,21.06 96.11,19.53 95.96,19.38 95.53,19.38 94.13,17.98 94.13,15.16 94.48,14.82 95.24,14.82 95.3,14.76 95.3,14.3 95.28,14.27 94.74,14.27 94.44,13.97 94.44,12.67 94.74,12.37 95.2,12.37 95.4,12.17 95.4,12.01 95.28,11.89 91.87,11.89 91.47,11.48 89.56,11.48
D on TOP (solid shape): 90.12,2.24 85.9,2.24 85.9,6.27 90.12,6.27
D on TOP: 91.74,5.11 91.74,5.08 91.8,5.13 94.44,5.13 94.82,4.75 94.82,2.08 95.2,1.7 97.08,1.7 97.62,2.25 97.62,2.83 98.35,3.56 99.97,3.56 100.76,2.77 100.74,2.74 100.74,1.17 99.8,0.23 78.44,0.23 78.26,0.41 78.26,10.59 78.28,10.59 78.26,10.62 78.26,13.28 78.36,13.39 80.26,13.39 80.37,13.28 80.37,9.53 80.39,9.5 80.39,9.19 79.73,8.53 79.73,7.24 80.15,6.82 81.56,6.82 83.3,8.56 84.07,8.56 85.19,7.44 85.19,6.48 85.42,6.25 90.6,6.25
D on BOTTOM: 98.4,3.56 100.05,3.56 100.74,2.87 100.74,1.07 99.92,0.25 78.28,0.25 78.28,12.9 78.79,13.41 80.64,13.41 80.64,13 80.29,12.65 80.29,9.07 79.73,8.51 79.73,7.21 80.12,6.82 81.74,6.82 82.33,7.41 82.33,8.31 82.58,8.56 84.48,8.56 84.73,8.31 84.73,6.86 84.7,6.82 85.09,6.43 85.12,6.43 85.19,6.35 90.17,6.35 90.35,6.17 90.35,4.52 91.36,3.51 91.36,3.05 92.74,1.68 97.05,1.68 97.64,2.26 97.64,2.79
Net_1 on TOP (solid shape): 102.62,19.48 102.62,17.3 102.01,16.69 100.48,16.69 100.13,17.04 100.13,18.34 100.43,18.64 100.43,19.46 100.97,19.99 102.11,19.99
SR on TOP: 86.31,8.66 85.47,8.66 85.04,9.09 85.04,9.35 84.89,9.5 84.68,9.5 84.61,9.42 84.61,8.79 85.55,7.85 85.55,7.57 85.72,7.39 86.31,7.39
N10479111 on BOTTOM (solid shape): 1.93,17.22 1.93,16.7 2.6,16.04 2.6,14 2.8,13.8 4.1,13.8 4.6,13.3 4.6,12.3 3.94,11.65 1.94,11.65 0.25,13.34 0.25,17.22 0.53,18.06 0.81,17.22 1.09,18.06 1.37,17.22 1.65,18.06
N10805923 on TOP: 32.92,17.17 34.52,17.17 35.13,16.56 35.13,12.04 34.65,11.56 33.05,11.56 32.82,11.79 32.82,17.07
N10805923 on TOP: 45.35,5.19 46.27,4.27 47.09,4.27 47.4,3.96 47.4,3.61 47.09,3.3 45.3,3.3 43.55,5.05 43.55,5.17 43.54,5.18 43.54,12.24 44,12.7 45.97,12.7 47.14,11.53 47.19,11.53 47.19,9.98 45.35,8.14
N10805923 on TOP: 26.59,15.49 27.99,15.49 28.17,15.32 28.17,13.18 27.97,12.98 26.64,12.98 26.59,13.03
N10805923 on TOP: 52.11,6.71 53.3,7.9 53.3,16.3 52.91,16.69 52.91,24.38 53.21,24.69 58.93,24.69 58.93,23.6 59.36,23.16 59.84,23.16 60.43,22.58 60.43,3.4 59.59,2.57 50.37,2.57 49.63,3.3 49.63,5.77 50.58,6.71
N10805923 on TOP: 26.57,15.51 28.03,15.51 28.18,15.35 28.18,13.07 28.04,12.93 26.67,12.93 24.43,15.16 21.77,15.16 20.62,14.02 19.56,14.02 17.45,16.13 16.89,16.13 16.89,19.02 17.17,19.3 25.86,19.3 26.57,18.59
N10805923 on TOP: 57.43,29.84 57.48,29.9 57.48,31.37 57.53,31.42 58.6,31.42 58.72,31.55 58.72,33.5 59.74,34.52 64.19,34.52 64.19,42.95 46.71,42.95 46.63,42.88 46.63,33.68 46.84,33.48 51.31,33.48 51.59,33.2 51.59,31.6 51.79,31.39 54.18,31.39 54.38,31.19 54.38,29.95 54.48,29.84
N10805923 on TOP: 52.91,26.44 52.91,24.13 53.21,23.83 58.93,23.83 58.93,26.52 58.8,26.64 53.11,26.64
N10805923 on BOTTOM: 52.93,26.44 52.93,24.13 53.24,23.83 58.93,23.83 58.93,26.52 58.8,26.64 53.14,26.64
N10805923 on BOTTOM: 51.49,31.47 51.54,31.42 54.15,31.42 54.38,31.19 54.38,29.95 54.51,29.82 57.4,29.82 57.48,29.9 57.48,31.37 58.62,31.37 58.75,31.5 58.75,33.12 57.81,34.06 56.46,34.06 56.06,34.47 56.06,35.89 56.46,36.3 56.46,38.25 56.44,38.28 51.59,38.28 51.49,38.18
N10805923 on BOTTOM: 50.06,21.06 52.93,23.93 52.93,24.23 58.93,24.23 58.93,23.57 59.36,23.14 59.49,23.14 59.51,23.16 59.82,23.16 60.4,22.58 60.4,4.9 59.7,4.2 53.36,4.2 53.28,4.28 53.28,11.39 53.31,11.43 53.31,16.28 51.82,17.78 50.14,17.78 50.1,17.74 45.17,17.74 44.55,18.36 44.42,18.36 44.27,18.21 45.72,16.76 45.7,12.9 45.9,12.7 45.9,12.7 47.14,11.46 47.14,9.96 46.82,9.63 45.37,9.63 44.7,10.3 43.8,10.3 43.5,10.6 43.56,18.26 43.26,18.26 43.21,18.21 43.21,13.21 41.53,11.53 33.02,11.53 32.82,11.73 32.82,16.92 33.1,17.2 34.34,17.2 34.39,17.14 40.61,17.14 42.37,18.9 42.37,20.04 43.38,21.06
N10805923 on BOTTOM: 26.62,15.51 28.04,15.51 28.04,15.49 28.21,15.33 28.21,13.12 28.02,12.93 26.62,12.93 26.62,12.95 24.13,15.44 18.11,15.44 17.45,16.1 16.92,16.1 16.92,19.02 17.17,19.28 25.88,19.28 26.59,18.57 26.59,15.53
N10806149 on TOP, BOTTOM: 60.2,26.62 61.39,26.62 61.54,26.47 61.54,24.94 61.34,24.74 60.15,24.74 59.92,24.97 59.92,26.34
N10806149 on TOP, BOTTOM: 60.15,33.25 61.34,33.25 61.54,33.05 61.54,31.62 61.29,31.37 60.1,31.37 59.87,31.6 59.87,32.97
N10961861 on TOP: 26.75,21.74 28.11,21.74 28.19,21.82 28.19,24.2 28.13,24.26 26.64,24.26 26.54,24.36 26.54,25.83 25.78,26.59 17.27,26.59 16.79,26.11 16.79,21.44 17.07,21.16 26.44,21.16 26.62,21.34 26.62,21.62
N10961861 on TOP: 32.94,26.59 32.84,26.49 32.84,20.95 33.4,20.4 36.2,20.4 37.82,18.77 39.73,18.77 40.01,19.05 40.01,25.91 39.32,26.59
N10961861 on TOP: 40.01,19.33 41.9,17.4 45.7,17.4 50,13.1 51.1,13.1 51.66,12.54 51.66,11.58 51.28,11.2 50.1,11.2 46,15.3 41.3,15.3 39.4,17.2 39.19,17.2 38.96,16.97 37.8,18.14 37.8,19.18 37.86,19.24 37.86,20.79 38.2,21.13 39.29,21.13 40.01,20.42
N10961861 on TOP: 26.72,24.26 28.12,24.26 28.19,24.18 28.19,21.84 28.09,21.74 26.77,21.74 26.72,21.79
N10961861 on TOP, BOTTOM: 62.89,33.25 64.08,33.25 64.29,33.05 64.29,31.62 64.03,31.37 62.84,31.37 62.61,31.6 62.61,32.97
N10961861 on BOTTOM: 35.05,26.59 32.99,26.59 32.84,26.44 32.84,20.95 33.43,20.37 34.67,20.37 35.94,19.1 39.73,19.1 39.73,23.24 39.78,23.29 39.78,23.8 38.14,23.8 37.8,23.46 35.4,23.46 35.15,23.7 35.15,26.49
N10961861 on BOTTOM: 26.75,21.74 28.11,21.74 28.2,21.84 28.2,24.19 28.13,24.26 26.49,24.26 26.49,25.88 25.83,26.54 17.53,26.54 16.89,25.91 16.89,21.34 17.07,21.16 26.44,21.16 26.59,21.31 26.59,21.59
N10966650 on TOP: 47.68,26.64 50.5,26.64 50.7,26.44 50.7,24.33 49.23,22.86 47.57,22.86 47.37,23.06 47.37,26.34
N10966650 on TOP: 48.59,29.82 48.59,31.34 49.58,31.34 49.58,29.82
N10966650 on BOTTOM: 47.65,26.64 50.47,26.64 50.67,26.44 50.67,24.92 48.62,22.86 47.35,22.86 47.35,26.34
N10966650 on BOTTOM: 49.7,31.53 49.53,31.37 49.53,29.82 48.64,29.82 48.62,29.84 48.62,37.67 49.2,38.25 49.68,38.25 49.7,38.24
N11036082 on BOTTOM: 41.61,26.01 44.78,26.01 46.38,24.41 46.38,22.86 46.35,22.83 43.69,22.83 43.15,22.3 41.61,22.3 41.55,22.35 41.55,25.96
N11077448 on BOTTOM: 47.45,4.81 46.44,4.81 46.41,4.85 46.41,6.93 45.9,7.44 45.9,7.59 46.41,8.1 46.81,8.1 47.82,7.1 48.63,7.1 48.68,7.05 48.68,5.62 48.24,5.62 47.45,4.83
N11099981 on TOP: 14.2,21.29 14.2,25.91 13.67,26.44 8.5,26.44 8.5,14.47 9.7,13.27 10.79,13.27 11.46,13.93 11.46,14.63 10.87,15.21 10.87,19.63 12.45,21.21 14.12,21.21
N11100009 on BOTTOM: 11.18,3.53 10.67,3.02 10.16,3.53 9.66,3.02 9.15,3.53 8.64,3.02 8.16,3.51 8.16,4.55 11.05,7.44 12.57,7.44 12.57,5.96 12.29,5.68 12.28,5.68 11.18,4.57
N11100013 on BOTTOM: 16.89,3.53 16.39,3.02 15.88,3.53 15.37,3.02 14.86,3.53 14.35,3.02 13.87,3.51 13.87,3.89 15.12,5.13 16.89,5.13
N11100013 on BOTTOM: 14.07,18.75 9.04,18.75 8.94,18.64 8.94,16.05 9.02,15.98 11.25,15.98 12.37,14.86 12.37,13.06 12.88,12.55 14.33,12.55 15.6,13.82 15.6,14.73 14.07,16.26
N11100133 on BOTTOM: 13.85,1.24 13.85,2.01 14.35,2.51 14.86,2.01 15.37,2.51 15.88,2.01 16.39,2.51 16.87,2.03 16.87,1.24 16.84,1.24 16.92,1.17 16.92,0.41 14.69,0.41
N11120095 on BOTTOM: 51.6,9.1 51.1,9.6 50.4,9.6 49.81,9.01 49.81,8.16 49.81,8.15 50.27,7.7 50.29,7.7 50.47,7.52 50.47,5.84 50.6,5.71 51.13,5.71 51.6,6.18
N11139619 on BOTTOM: 36.27,24.23 36.27,26.29 36.5,26.52 39.17,26.52 39.73,25.96 39.73,24.56 39.7,24.54 37.87,24.54 37.52,24.18 36.32,24.18
N11156493 on BOTTOM: 82.04,12.6 83.59,12.6 84.02,12.17 84.02,9.14 82.04,9.14
N12330267 on BOTTOM: 7.11,2.01 8.13,2.01 8.64,2.51 9.15,2.01 9.66,2.51 10.16,2.01 10.67,2.51 11.15,2.03 11.15,1.14 10.52,0.51 6.61,0.51 5.56,1.56 2.51,4.6 2.51,8.03 3,8.51 4.29,8.51 4.88,7.92 4.88,4.24

Small or netless copper shapes (teardrops, artwork), in the pictures only: 2 on BOTTOM

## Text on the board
Ref Des/Silkscreen Bottom: BD 1 | 1943 | REV B | DER-600 | BD 3 | S/N
Ref Des/Silkscreen Top: C4-1 | L | SG | N | C4-2 | S/N | 1943 | REV B | DER-600 | BD 4 | BD 2
User.5: 14.  FAB HOUSE LOGO,DATE CODE TO BE IN SILK SCREEN ONLY.DO NOT USE COPPER. | 13.  MATERIAL FR4 COPPER 2oz THICKNESS 0.040" | PLEASE DELETE THESE PINS | 8SLOTS
User.8: FIGURE | FINISHED_SIZE | 12.0 | 16.0 | 20.0 | 24.0 | 25.0 | 30.0 | 35.0 | 40.0 | 48.0 | 68.0 | 47.201x23.598 | DRILL CHART: TOP to BOTTOM | ALL UNITS ARE IN MILS | TOLERANCE_DRILL | +3.0/-3.0 | +0.0/-0.0 | PLATED | QTY | 18 | 14 | 84 | 4 | 22 | 1 | 5 | 13 | 8 | 3 | 2
